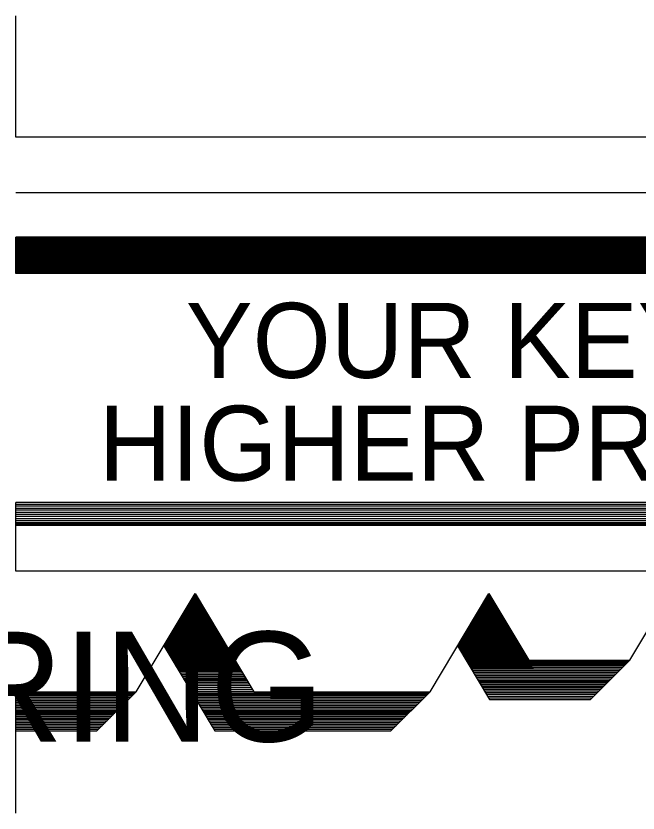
# Model space of a CAD drawing. Extents: x 22369.62 to 22376.4, y 22369.62 to 22372.46.
# Drawn here: x 22369.8691 to 22369.9158, y 22369.7135 to 22369.7734 of the extents above; entities that cross this region are included whole.
import ezdxf

# ---------------------------------------------------------------- set-up
doc = ezdxf.new("R2010")
doc.units = 0
for name, color, linetype in [('Level 1', 7, 'Continuous'), ('Level 10', 7, 'Continuous'), ('Level 2', 7, 'Continuous'), ('Level 7', 7, 'Continuous')]:
    doc.layers.add(name, color=color, linetype=linetype)

msp = doc.modelspace()

# ---------------------------------------------------------------- linework, layer by layer
at = {"layer": 'Level 1'}
msp.add_line((22369.869071, 22369.75405), (22369.869071, 22369.756769), dxfattribs=at)
at = {"layer": 'Level 10'}
msp.add_line((22369.959196, 22369.760123), (22369.869071, 22369.760123), dxfattribs=at)
at = {"layer": 'Level 2'}
for p, q in [((22369.963248, 22369.756769), (22369.869071, 22369.756769)), ((22369.963331, 22369.756706), (22369.869071, 22369.756706)), ((22369.963404, 22369.756644), (22369.869071, 22369.756644)), ((22369.963488, 22369.756571), (22369.869071, 22369.756571)), ((22369.963581, 22369.756498), (22369.869071, 22369.756498)), ((22369.963665, 22369.756425), (22369.869071, 22369.756425)), ((22369.963769, 22369.756342), (22369.869071, 22369.756342)), ((22369.963852, 22369.756269), (22369.869071, 22369.756269)), ((22369.963956, 22369.756185), (22369.869071, 22369.756185)), ((22369.96406, 22369.756102), (22369.869071, 22369.756102)), ((22369.964144, 22369.756029), (22369.869071, 22369.756029)), ((22369.964238, 22369.755946), (22369.869071, 22369.755946)), ((22369.964352, 22369.755863), (22369.869071, 22369.755863)), ((22369.964435, 22369.75579), (22369.869071, 22369.75579)), ((22369.964519, 22369.755717), (22369.869071, 22369.755717)), ((22369.964623, 22369.755633), (22369.869071, 22369.755633)), ((22369.964727, 22369.75555), (22369.869071, 22369.75555)), ((22369.964821, 22369.755467), (22369.869071, 22369.755467)), ((22369.964935, 22369.755373), (22369.869071, 22369.755373)), ((22369.965029, 22369.7553), (22369.869071, 22369.7553)), ((22369.965123, 22369.755217), (22369.869071, 22369.755217)), ((22369.965238, 22369.755123), (22369.869071, 22369.755123)), ((22369.965342, 22369.75504), (22369.869071, 22369.75504)), ((22369.965415, 22369.754977), (22369.869071, 22369.754977)), ((22369.965519, 22369.754894), (22369.869071, 22369.754894)), ((22369.965613, 22369.75481), (22369.869071, 22369.75481)), ((22369.965706, 22369.754738), (22369.869071, 22369.754738)), ((22369.96579, 22369.754665), (22369.869071, 22369.754665)), ((22369.965873, 22369.754602), (22369.869071, 22369.754602)), ((22369.965988, 22369.754508), (22369.869071, 22369.754508)), ((22369.96606, 22369.754446), (22369.869071, 22369.754446)), ((22369.966144, 22369.754373), (22369.869071, 22369.754373)), ((22369.966217, 22369.75431), (22369.869071, 22369.75431)), ((22369.9663, 22369.754248), (22369.869071, 22369.754248)), ((22369.966363, 22369.754196), (22369.869071, 22369.754196)), ((22369.966435, 22369.754133), (22369.869071, 22369.754133)), ((22369.966488, 22369.754092), (22369.869071, 22369.754092)), ((22369.96654, 22369.75405), (22369.869071, 22369.75405)), ((22369.971363, 22369.736842), (22369.869071, 22369.736842)), ((22369.869071, 22369.731675), (22369.869071, 22369.736842)), ((22369.971196, 22369.736706), (22369.869071, 22369.736706)), ((22369.971019, 22369.73656), (22369.869071, 22369.73656)), ((22369.970821, 22369.736394), (22369.869071, 22369.736394)), ((22369.970654, 22369.736258), (22369.869071, 22369.736258)), ((22369.970456, 22369.736092), (22369.869071, 22369.736092)), ((22369.970279, 22369.735946), (22369.869071, 22369.735946)), ((22369.970092, 22369.73579), (22369.869071, 22369.73579)), ((22369.969883, 22369.735623), (22369.869071, 22369.735623)), ((22369.969696, 22369.735467), (22369.869071, 22369.735467)), ((22369.969519, 22369.735321), (22369.869071, 22369.735321)), ((22369.969394, 22369.735217), (22369.869071, 22369.735217)), ((22369.969279, 22369.735123), (22369.869071, 22369.735123)), ((22369.965113, 22369.731675), (22369.869071, 22369.731675)), ((22369.90454, 22369.729925), (22369.904644, 22369.729925)), ((22369.882165, 22369.729404), (22369.882894, 22369.729404)), ((22369.882217, 22369.729488), (22369.882842, 22369.729488)), ((22369.882269, 22369.729571), (22369.88279, 22369.729571)), ((22369.882321, 22369.729654), (22369.882738, 22369.729654)), ((22369.882363, 22369.729738), (22369.882696, 22369.729738)), ((22369.882415, 22369.729821), (22369.882644, 22369.729821)), ((22369.882467, 22369.729904), (22369.882592, 22369.729904)), ((22369.904227, 22369.729404), (22369.904956, 22369.729404)), ((22369.904279, 22369.729488), (22369.904904, 22369.729488)), ((22369.904331, 22369.729571), (22369.904852, 22369.729571)), ((22369.904383, 22369.729654), (22369.9048, 22369.729654)), ((22369.904425, 22369.729738), (22369.904758, 22369.729738)), ((22369.904467, 22369.7298), (22369.904717, 22369.7298)), ((22369.904508, 22369.729863), (22369.904675, 22369.729863)), ((22369.881779, 22369.728738), (22369.88329, 22369.728738)), ((22369.881831, 22369.728821), (22369.883238, 22369.728821)), ((22369.881863, 22369.728904), (22369.883185, 22369.728904)), ((22369.881915, 22369.728988), (22369.883144, 22369.728988)), ((22369.881967, 22369.729071), (22369.883092, 22369.729071)), ((22369.882019, 22369.729154), (22369.88304, 22369.729154)), ((22369.882071, 22369.729238), (22369.882988, 22369.729238)), ((22369.882113, 22369.729321), (22369.882935, 22369.729321)), ((22369.903842, 22369.728738), (22369.905352, 22369.728738)), ((22369.903894, 22369.728821), (22369.9053, 22369.728821)), ((22369.903925, 22369.728904), (22369.905248, 22369.728904)), ((22369.903977, 22369.728988), (22369.905206, 22369.728988)), ((22369.904029, 22369.729071), (22369.905154, 22369.729071)), ((22369.904081, 22369.729154), (22369.905102, 22369.729154)), ((22369.904133, 22369.729238), (22369.90505, 22369.729238)), ((22369.904175, 22369.729321), (22369.904998, 22369.729321)), ((22369.881415, 22369.728154), (22369.883633, 22369.728154)), ((22369.881467, 22369.728238), (22369.883592, 22369.728238)), ((22369.881519, 22369.728321), (22369.88354, 22369.728321)), ((22369.881571, 22369.728404), (22369.883488, 22369.728404)), ((22369.881623, 22369.728488), (22369.883435, 22369.728488)), ((22369.881675, 22369.728571), (22369.883394, 22369.728571)), ((22369.881727, 22369.728654), (22369.883342, 22369.728654)), ((22369.903477, 22369.728154), (22369.905696, 22369.728154)), ((22369.903529, 22369.728238), (22369.905654, 22369.728238)), ((22369.903581, 22369.728321), (22369.905602, 22369.728321)), ((22369.903633, 22369.728404), (22369.90555, 22369.728404)), ((22369.903685, 22369.728488), (22369.905498, 22369.728488)), ((22369.903738, 22369.728571), (22369.905456, 22369.728571)), ((22369.90379, 22369.728654), (22369.905404, 22369.728654)), ((22369.881071, 22369.727571), (22369.883988, 22369.727571)), ((22369.881123, 22369.727654), (22369.883935, 22369.727654)), ((22369.881165, 22369.727738), (22369.883883, 22369.727738)), ((22369.881217, 22369.727821), (22369.883842, 22369.727821)), ((22369.881269, 22369.727904), (22369.88379, 22369.727904)), ((22369.881321, 22369.727988), (22369.883738, 22369.727988)), ((22369.881373, 22369.728071), (22369.883685, 22369.728071)), ((22369.903133, 22369.727571), (22369.90605, 22369.727571)), ((22369.903185, 22369.727654), (22369.905998, 22369.727654)), ((22369.903227, 22369.727738), (22369.905946, 22369.727738)), ((22369.903279, 22369.727821), (22369.905904, 22369.727821)), ((22369.903331, 22369.727904), (22369.905852, 22369.727904)), ((22369.903383, 22369.727988), (22369.9058, 22369.727988)), ((22369.903435, 22369.728071), (22369.905748, 22369.728071)), ((22369.880727, 22369.726988), (22369.884331, 22369.726988)), ((22369.880779, 22369.727071), (22369.88429, 22369.727071)), ((22369.880831, 22369.727154), (22369.884238, 22369.727154)), ((22369.880883, 22369.727238), (22369.884185, 22369.727238)), ((22369.880935, 22369.727321), (22369.884133, 22369.727321)), ((22369.880988, 22369.727404), (22369.884092, 22369.727404)), ((22369.881019, 22369.727488), (22369.88404, 22369.727488)), ((22369.90279, 22369.726988), (22369.906394, 22369.726988)), ((22369.902842, 22369.727071), (22369.906352, 22369.727071)), ((22369.902894, 22369.727154), (22369.9063, 22369.727154)), ((22369.902946, 22369.727238), (22369.906248, 22369.727238)), ((22369.902998, 22369.727321), (22369.906196, 22369.727321)), ((22369.90305, 22369.727404), (22369.906154, 22369.727404)), ((22369.903081, 22369.727488), (22369.906102, 22369.727488)), ((22369.880373, 22369.726404), (22369.884685, 22369.726404)), ((22369.880415, 22369.726488), (22369.884633, 22369.726488)), ((22369.880467, 22369.726571), (22369.884581, 22369.726571)), ((22369.880519, 22369.726654), (22369.88454, 22369.726654)), ((22369.880571, 22369.726738), (22369.884488, 22369.726738)), ((22369.880623, 22369.726821), (22369.884435, 22369.726821)), ((22369.880675, 22369.726904), (22369.884383, 22369.726904)), ((22369.902435, 22369.726404), (22369.906748, 22369.726404)), ((22369.902477, 22369.726488), (22369.906696, 22369.726488)), ((22369.902529, 22369.726571), (22369.906644, 22369.726571)), ((22369.902581, 22369.726654), (22369.906602, 22369.726654)), ((22369.902633, 22369.726738), (22369.90655, 22369.726738)), ((22369.902685, 22369.726821), (22369.906498, 22369.726821)), ((22369.902738, 22369.726904), (22369.906446, 22369.726904)), ((22369.880175, 22369.726071), (22369.883998, 22369.719675)), ((22369.880175, 22369.726071), (22369.884883, 22369.726071)), ((22369.880217, 22369.726154), (22369.884831, 22369.726154)), ((22369.880227, 22369.725988), (22369.884935, 22369.725988)), ((22369.880269, 22369.726238), (22369.884779, 22369.726238)), ((22369.880279, 22369.725904), (22369.884988, 22369.725904)), ((22369.880321, 22369.726321), (22369.884738, 22369.726321)), ((22369.880321, 22369.725821), (22369.885029, 22369.725821)), ((22369.880373, 22369.725738), (22369.885081, 22369.725738)), ((22369.902238, 22369.726071), (22369.904654, 22369.72205)), ((22369.902238, 22369.726071), (22369.906946, 22369.726071)), ((22369.902279, 22369.726154), (22369.906894, 22369.726154)), ((22369.90229, 22369.725988), (22369.906998, 22369.725988)), ((22369.902331, 22369.726238), (22369.906842, 22369.726238)), ((22369.902342, 22369.725904), (22369.90705, 22369.725904)), ((22369.902383, 22369.726321), (22369.9068, 22369.726321)), ((22369.902383, 22369.725821), (22369.907092, 22369.725821)), ((22369.902435, 22369.725738), (22369.907144, 22369.725738)), ((22369.880425, 22369.725654), (22369.885113, 22369.725654)), ((22369.880477, 22369.725571), (22369.885165, 22369.725571)), ((22369.880519, 22369.725488), (22369.885217, 22369.725488)), ((22369.880571, 22369.725404), (22369.885269, 22369.725404)), ((22369.880623, 22369.725321), (22369.885321, 22369.725321)), ((22369.880675, 22369.725238), (22369.885373, 22369.725238)), ((22369.880727, 22369.725154), (22369.885425, 22369.725154)), ((22369.902488, 22369.725654), (22369.907175, 22369.725654)), ((22369.90254, 22369.725571), (22369.907227, 22369.725571)), ((22369.902581, 22369.725488), (22369.907279, 22369.725488)), ((22369.902633, 22369.725404), (22369.907331, 22369.725404)), ((22369.902685, 22369.725321), (22369.907383, 22369.725321)), ((22369.902738, 22369.725238), (22369.907435, 22369.725238)), ((22369.90279, 22369.725154), (22369.907488, 22369.725154)), ((22369.880769, 22369.725071), (22369.885477, 22369.725071)), ((22369.880821, 22369.724988), (22369.885529, 22369.724988)), ((22369.880873, 22369.724904), (22369.885581, 22369.724904)), ((22369.880915, 22369.724842), (22369.885623, 22369.724842)), ((22369.880956, 22369.724758), (22369.885665, 22369.724758)), ((22369.881008, 22369.724675), (22369.885717, 22369.724675)), ((22369.88106, 22369.724581), (22369.885779, 22369.724581)), ((22369.902831, 22369.725071), (22369.90754, 22369.725071)), ((22369.902883, 22369.724988), (22369.907592, 22369.724988)), ((22369.902935, 22369.724904), (22369.907644, 22369.724904)), ((22369.902977, 22369.724842), (22369.907685, 22369.724842)), ((22369.903019, 22369.724758), (22369.907727, 22369.724758)), ((22369.903071, 22369.724675), (22369.907779, 22369.724675)), ((22369.903123, 22369.724581), (22369.907842, 22369.724581)), ((22369.906154, 22369.724894), (22369.915081, 22369.724894)), ((22369.906154, 22369.7248), (22369.914988, 22369.7248)), ((22369.906154, 22369.724706), (22369.914894, 22369.724706)), ((22369.906154, 22369.724592), (22369.914779, 22369.724592)), ((22369.912238, 22369.72205), (22369.915185, 22369.724998)), ((22369.881123, 22369.724477), (22369.885842, 22369.724477)), ((22369.881185, 22369.724383), (22369.885894, 22369.724383)), ((22369.881248, 22369.724269), (22369.885967, 22369.724269)), ((22369.88131, 22369.724165), (22369.886019, 22369.724165)), ((22369.881394, 22369.72404), (22369.886102, 22369.72404)), ((22369.903185, 22369.724477), (22369.907904, 22369.724477)), ((22369.903248, 22369.724383), (22369.907956, 22369.724383)), ((22369.903279, 22369.724342), (22369.914529, 22369.724342)), ((22369.903352, 22369.724217), (22369.914404, 22369.724217)), ((22369.903425, 22369.724092), (22369.914279, 22369.724092)), ((22369.903498, 22369.723977), (22369.914165, 22369.723977)), ((22369.906154, 22369.724477), (22369.914665, 22369.724477)), ((22369.881456, 22369.723925), (22369.886165, 22369.723925)), ((22369.881529, 22369.7238), (22369.886238, 22369.7238)), ((22369.881602, 22369.723675), (22369.886321, 22369.723675)), ((22369.881665, 22369.723571), (22369.886383, 22369.723571)), ((22369.881727, 22369.723467), (22369.886446, 22369.723467)), ((22369.88181, 22369.723342), (22369.886519, 22369.723342)), ((22369.903571, 22369.723852), (22369.91404, 22369.723852)), ((22369.903644, 22369.723727), (22369.913915, 22369.723727)), ((22369.903717, 22369.723602), (22369.91379, 22369.723602)), ((22369.9038, 22369.723477), (22369.913665, 22369.723477)), ((22369.903842, 22369.723394), (22369.913581, 22369.723394)), ((22369.881873, 22369.723227), (22369.886581, 22369.723227)), ((22369.881946, 22369.723102), (22369.886654, 22369.723102)), ((22369.88205, 22369.722935), (22369.886758, 22369.722935)), ((22369.882133, 22369.7228), (22369.886842, 22369.7228)), ((22369.903904, 22369.7233), (22369.913488, 22369.7233)), ((22369.903977, 22369.723175), (22369.913363, 22369.723175)), ((22369.90405, 22369.72305), (22369.913238, 22369.72305)), ((22369.904113, 22369.722946), (22369.913133, 22369.722946)), ((22369.904196, 22369.72281), (22369.912998, 22369.72281)), ((22369.869071, 22369.722519), (22369.877998, 22369.722519)), ((22369.869071, 22369.722425), (22369.877904, 22369.722425)), ((22369.869071, 22369.722331), (22369.87781, 22369.722331)), ((22369.869071, 22369.722217), (22369.877696, 22369.722217)), ((22369.875154, 22369.719675), (22369.878102, 22369.722623)), ((22369.882217, 22369.722654), (22369.886925, 22369.722654)), ((22369.8823, 22369.722519), (22369.900071, 22369.722519)), ((22369.882352, 22369.722425), (22369.899977, 22369.722425)), ((22369.882415, 22369.722331), (22369.899883, 22369.722331)), ((22369.882477, 22369.722217), (22369.899769, 22369.722217)), ((22369.897227, 22369.719675), (22369.900175, 22369.722623)), ((22369.904269, 22369.722685), (22369.912873, 22369.722685)), ((22369.904352, 22369.72256), (22369.912748, 22369.72256)), ((22369.904415, 22369.722446), (22369.912633, 22369.722446)), ((22369.904508, 22369.7223), (22369.912488, 22369.7223)), ((22369.904581, 22369.722175), (22369.912363, 22369.722175)), ((22369.869071, 22369.722102), (22369.877581, 22369.722102)), ((22369.869071, 22369.721967), (22369.877446, 22369.721967)), ((22369.869071, 22369.721842), (22369.877321, 22369.721842)), ((22369.869071, 22369.721717), (22369.877196, 22369.721717)), ((22369.869071, 22369.721602), (22369.877081, 22369.721602)), ((22369.88255, 22369.722102), (22369.899654, 22369.722102)), ((22369.882633, 22369.721967), (22369.899519, 22369.721967)), ((22369.882706, 22369.721842), (22369.899394, 22369.721842)), ((22369.882779, 22369.721717), (22369.899269, 22369.721717)), ((22369.882842, 22369.721602), (22369.899154, 22369.721602)), ((22369.904654, 22369.72205), (22369.912238, 22369.72205)), ((22369.869071, 22369.721477), (22369.876956, 22369.721477)), ((22369.869071, 22369.721352), (22369.876831, 22369.721352)), ((22369.869071, 22369.721227), (22369.876706, 22369.721227)), ((22369.869071, 22369.721102), (22369.876581, 22369.721102)), ((22369.869071, 22369.721019), (22369.876498, 22369.721019)), ((22369.882925, 22369.721477), (22369.899029, 22369.721477)), ((22369.882998, 22369.721352), (22369.898904, 22369.721352)), ((22369.883071, 22369.721227), (22369.898779, 22369.721227)), ((22369.883144, 22369.721102), (22369.898654, 22369.721102)), ((22369.883196, 22369.721019), (22369.898571, 22369.721019)), ((22369.869071, 22369.720925), (22369.876404, 22369.720925)), ((22369.869071, 22369.7208), (22369.876279, 22369.7208)), ((22369.869071, 22369.720675), (22369.876154, 22369.720675)), ((22369.869071, 22369.720571), (22369.87605, 22369.720571)), ((22369.869071, 22369.720435), (22369.875915, 22369.720435)), ((22369.883248, 22369.720925), (22369.898477, 22369.720925)), ((22369.883321, 22369.7208), (22369.898352, 22369.7208)), ((22369.883404, 22369.720675), (22369.898227, 22369.720675)), ((22369.883467, 22369.720571), (22369.898123, 22369.720571)), ((22369.88354, 22369.720435), (22369.897988, 22369.720435)), ((22369.869071, 22369.72031), (22369.87579, 22369.72031)), ((22369.869071, 22369.720185), (22369.875665, 22369.720185)), ((22369.869071, 22369.720071), (22369.87555, 22369.720071)), ((22369.869071, 22369.719925), (22369.875404, 22369.719925)), ((22369.869071, 22369.7198), (22369.875279, 22369.7198)), ((22369.883623, 22369.72031), (22369.897863, 22369.72031)), ((22369.883696, 22369.720185), (22369.897738, 22369.720185)), ((22369.883758, 22369.720071), (22369.897623, 22369.720071)), ((22369.883852, 22369.719925), (22369.897477, 22369.719925)), ((22369.883925, 22369.7198), (22369.897352, 22369.7198)), ((22369.869071, 22369.719675), (22369.875154, 22369.719675)), ((22369.883998, 22369.719675), (22369.897227, 22369.719675))]:
    msp.add_line(p, q, dxfattribs=at)
at = {"layer": 'Level 7'}
for p, q in [((22369.869071, 22369.76429), (22369.869071, 22369.773404)), ((22369.954154, 22369.76429), (22369.869071, 22369.76429)), ((22369.878102, 22369.722623), (22369.882529, 22369.730008)), ((22369.882529, 22369.730008), (22369.886946, 22369.722623)), ((22369.900175, 22369.722623), (22369.904592, 22369.730008)), ((22369.904592, 22369.730008), (22369.907602, 22369.724998)), ((22369.915185, 22369.724998), (22369.918185, 22369.730008)), ((22369.907602, 22369.724998), (22369.915185, 22369.724998)), ((22369.869071, 22369.713508), (22369.869071, 22369.722623)), ((22369.869071, 22369.722623), (22369.878102, 22369.722623)), ((22369.886946, 22369.722623), (22369.900175, 22369.722623))]:
    msp.add_line(p, q, dxfattribs=at)

# ---------------------------------------------------------------- texts
at = {"layer": 'Level 2'}
for s, height, p in [('YOUR KEY TO', 0.00564056, (22369.881821, 22369.746206)), ('HIGHER PROFITS', 0.00564056, (22369.8753, 22369.738477)), ('ENGINEERING', 0.00824938, (22369.814998, 22369.718883))]:
    msp.add_text(s, height=height, dxfattribs=at).set_placement(p)

doc.saveas('drawing.dxf')
